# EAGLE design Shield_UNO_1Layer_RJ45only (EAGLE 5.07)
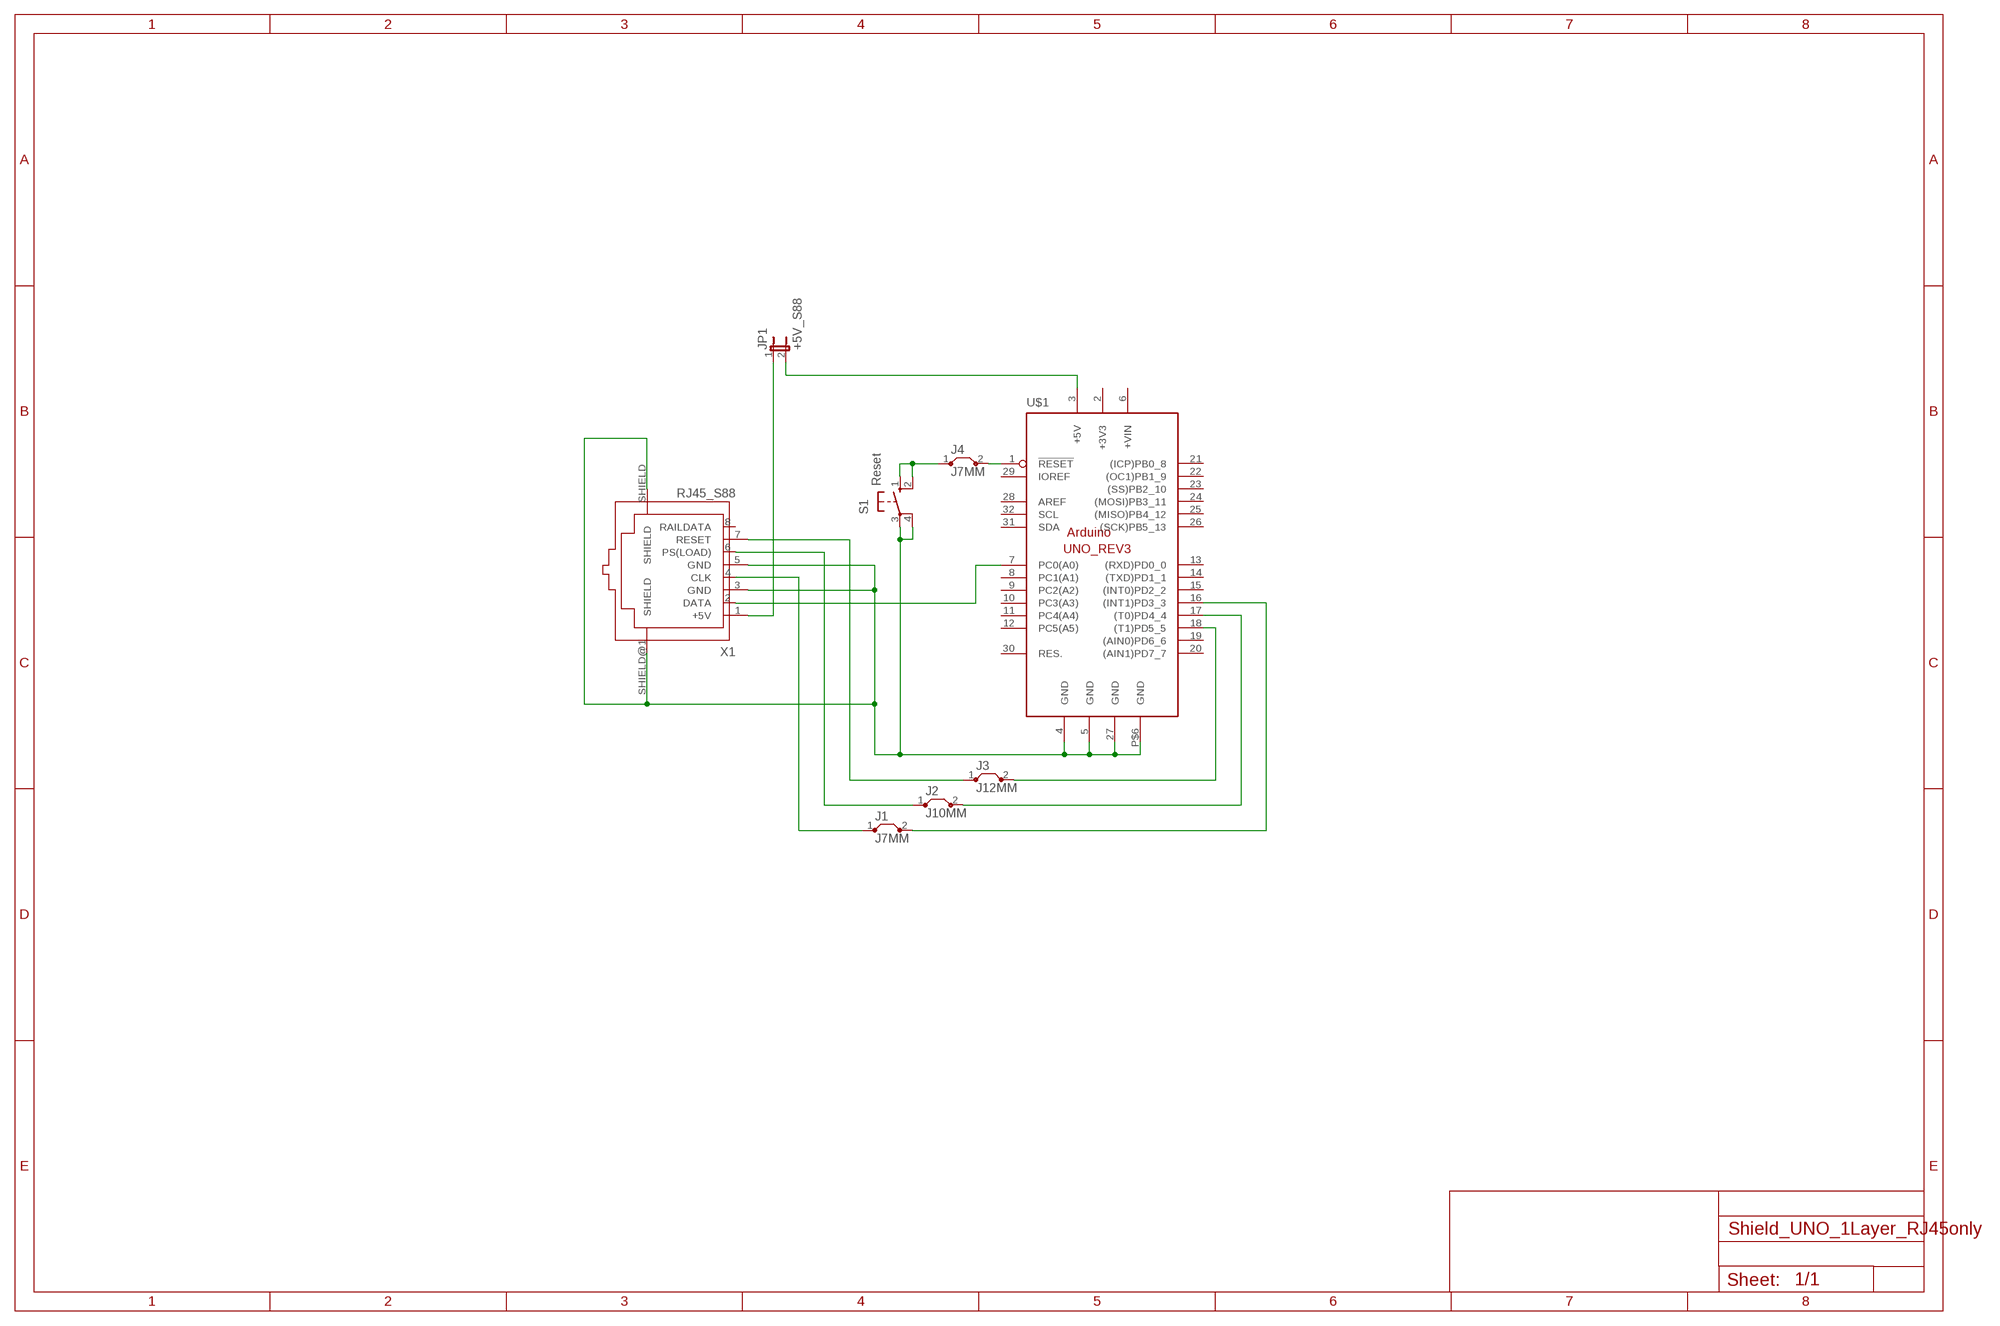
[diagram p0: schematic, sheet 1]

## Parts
J1  J7MM  [07]
J2  J10MM  [10]
J3  J12MM  [12]
J4  J7MM  [07]
JP1  +5V_S88  JP1E  [JP1]
S1  Reset  10-XX  [B3F-10XX]
U$1  ARDUINO_UNO_REV3  [ARDUINO_UNO_REV3_SHORT]
X1  RJ45_S88  RJ45-S88-N  [RJ45-SHIELDED]

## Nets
GND: S1.3(P) S1.4(P1) U$1.4(GND) U$1.5(GND) U$1.27(GND) U$1.P$6(GND) X1.3(GND) X1.5(GND) X1.SHIELD X1.SHIELD@1(SHIELD)
N$1: J4.1 S1.1(S) S1.2(S1)
N$2: J1.2 U$1.16((INT1)PD3_3)
N$3: JP1.2 U$1.3(+5V)
N$4: U$1.7(PC0(A0)) X1.2(DATA)
N$5: J2.2 U$1.17((T0)PD4_4)
N$6: J4.2 U$1.1(!RESET)
N$7: J3.2 U$1.18((T1)PD5_5)
N$8: J3.1 X1.7(RESET)
N$9: J2.1 X1.6(PS(LOAD))
N$10: J1.1 X1.4(CLK)
N$11: JP1.1 X1.1(+5V)
Unconnected: U$1.6(+VIN) U$1.8(PC1(A1)) U$1.9(PC2(A2)) U$1.10(PC3(A3)) U$1.11(PC4(A4)) U$1.12(PC5(A5)) U$1.13((RXD)PD0_0) U$1.14((TXD)PD1_1) U$1.15((INT0)PD2_2) U$1.19((AIN0)PD6_6) U$1.20((AIN1)PD7_7) U$1.21((ICP)PB0_8) U$1.22((OC1)PB1_9) U$1.23((SS)PB2_10) U$1.24((MOSI)PB3_11) U$1.25((MISO)PB4_12) U$1.26((SCK)PB5_13) U$1.28(AREF) U$1.29(IOREF) U$1.30(RES.) U$1.31(SDA) U$1.32(SCL) X1.8(RAILDATA)

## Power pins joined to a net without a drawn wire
+3V3: U$1.2(+3V3)

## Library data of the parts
J1-J4 = jumper:J: Bridge
JP1 = jumper:JP1E: JUMPER
S1 = switch-omron:10-XX: OMRON SWITCH
U$1 = arduino:ARDUINO_UNO_REV3
X1 = con-amphenol-rj45_S88-N:RJ45-S88-N: RJ45 socket Naming: BEL FUSESS-7188S-A-NF TMESS-7188S-A-NF Datasheet: https://www.belfuse.com/resources/drawings/stewartconnector/dr-stw-ss-7188s-a-nf-ss-7188s-a-nf-50.pdf

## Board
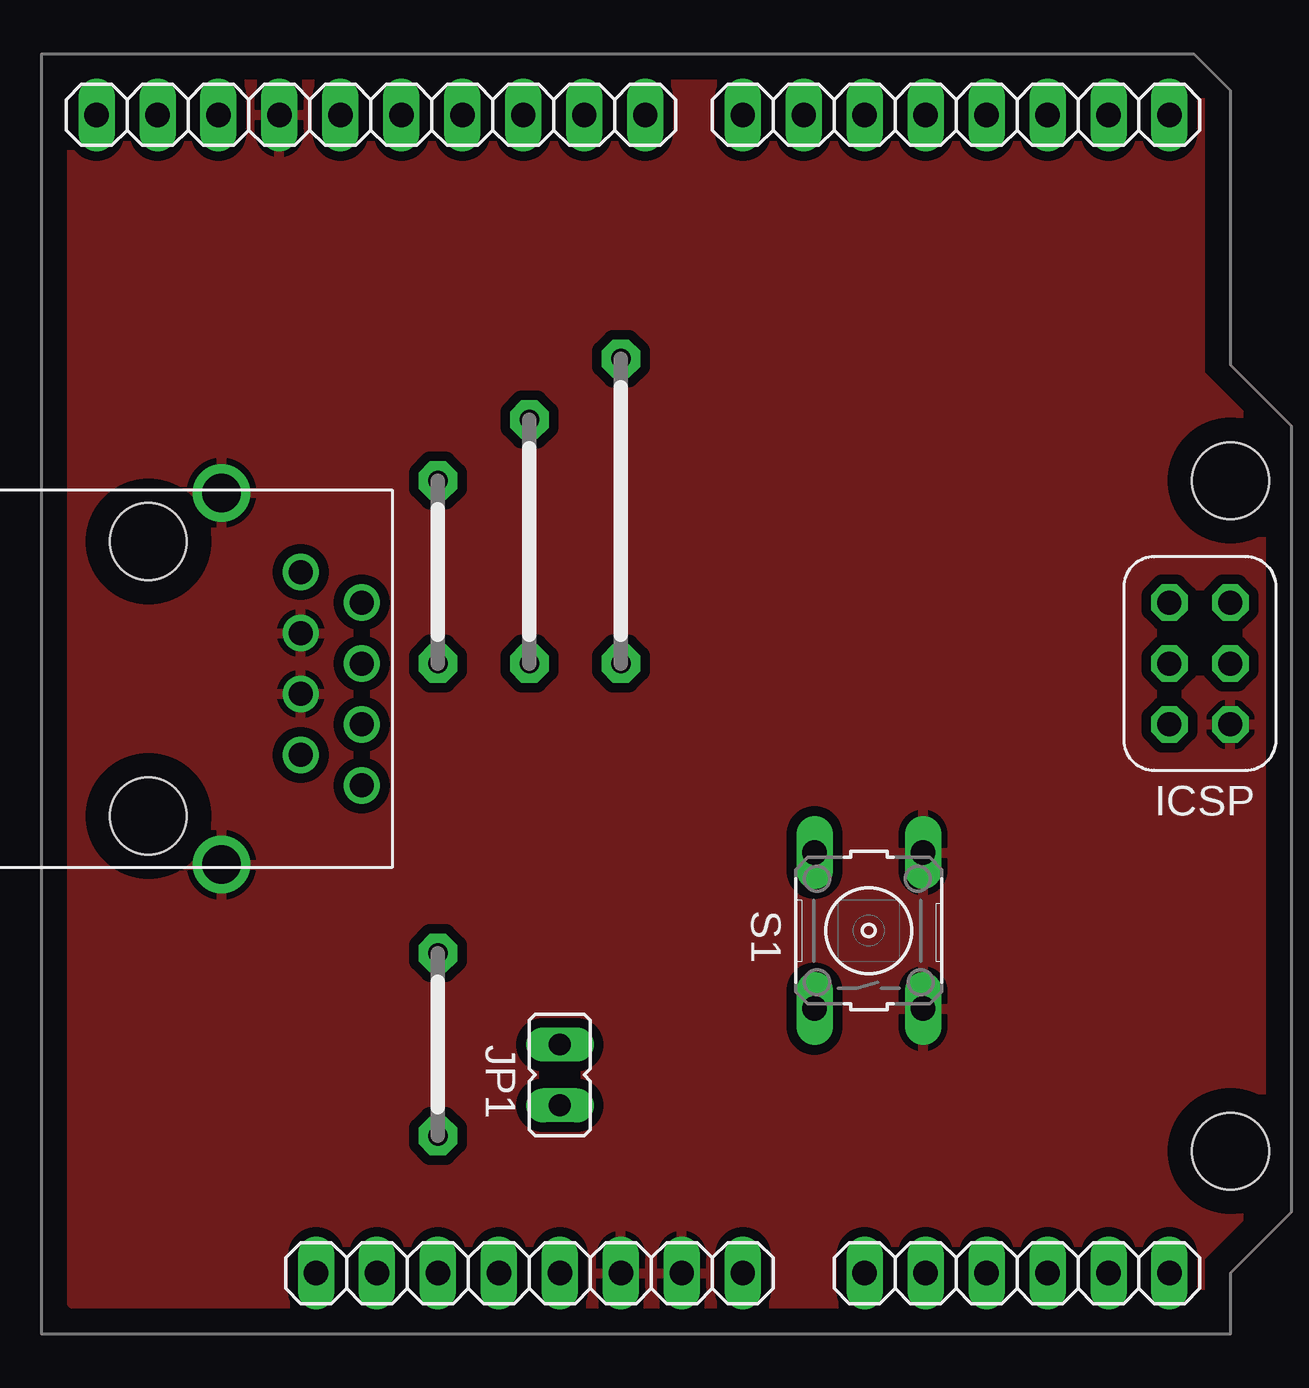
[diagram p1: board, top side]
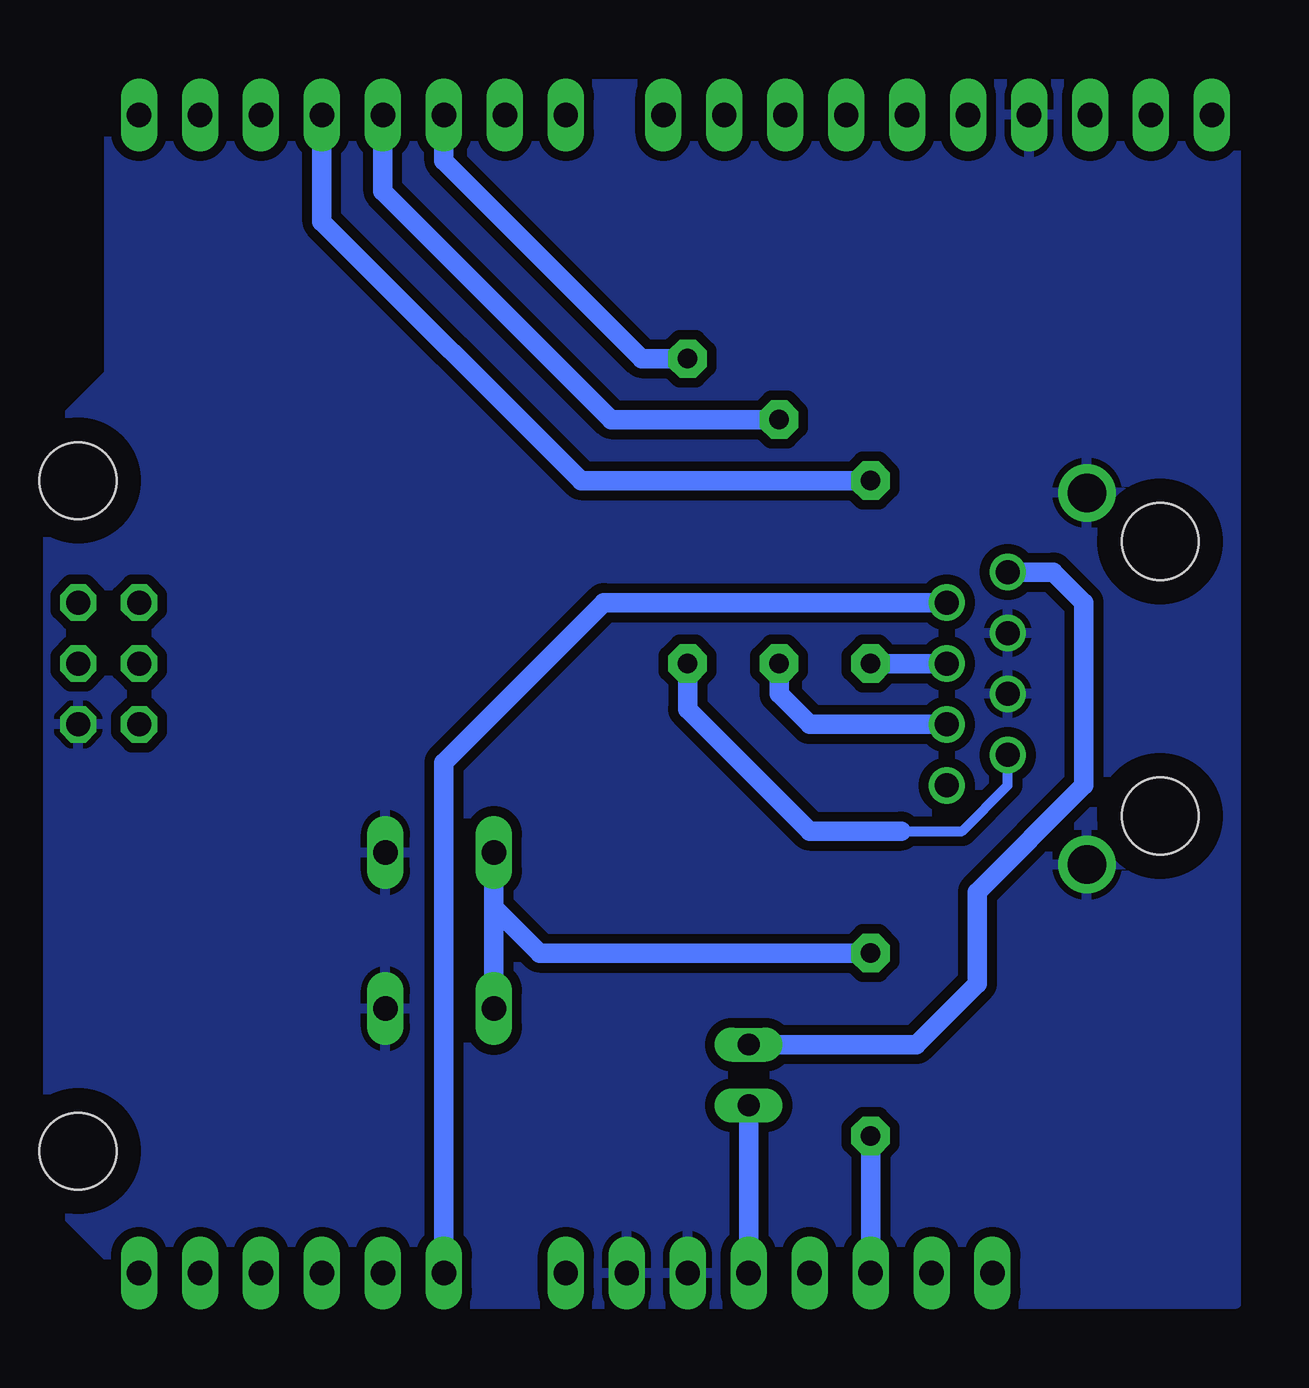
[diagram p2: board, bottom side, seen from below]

No outline drawn. Coordinates in mm, seen from the top.
Copper layers (1*16): Top 0.035mm / dielectric 1.5mm / Bottom 0.035mm
Design rules "default *": minimum track width 16mil, minimum drill 24mil, track to track 16mil, track to pad 16mil, pad to pad 16mil, via to via 16mil, smd to smd 10mil, copper to edge 40mil, drill to drill 20mil, minimum pad ring 10mil, minimum via ring 8mil, stop-mask expansion 4mil, vias tented up to drill 0mil, thermal gap 10mil

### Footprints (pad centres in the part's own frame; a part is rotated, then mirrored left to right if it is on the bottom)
07 = drill 0.813 pad 1.6 octagon: 1 -3.81,0; 2 3.81,0
10 = drill 0.813 pad 1.6 octagon: 1 -5.08,0; 2 5.08,0
12 = drill 0.813 pad 1.6 octagon: 1 -6.35,0; 2 6.35,0
JP1 = drill 0.914 long: 1 0,-1.27; 2 0,1.27
B3F-10XX = drill 1.016 long: 1 -3.251,2.261; 2 3.251,2.261; 3 -3.251,-2.261; 4 3.251,-2.261
ARDUINO_UNO_REV3_SHORT = drill 1.016 long: 1 33.02,2.54; 2 35.56,2.54; 3 38.1,2.54; 4 40.64,2.54; 5 43.18,2.54; 6 45.72,2.54; 7 50.8,2.54; 8 53.34,2.54; 9 55.88,2.54; 10 58.42,2.54; 11 60.96,2.54; 12 63.5,2.54; 13 63.5,50.8; 14 60.96,50.8; 15 58.42,50.8; 16 55.88,50.8; 17 53.34,50.8; 18 50.8,50.8; 19 48.26,50.8; 20 45.72,50.8; 21 41.656,50.8; 22 39.116,50.8; 23 36.576,50.8; 24 34.036,50.8; 25 31.496,50.8; 26 28.956,50.8; 27 26.416,50.8; 28 23.876,50.8; 29 30.48,2.54; 30 27.94,2.54; 31 21.336,50.8; 32 18.796,50.8 | drill 1 octagon: P$1 63.5,30.48; P$2 66.04,30.48; P$3 66.04,27.94; P$4 63.5,27.94; P$5 63.5,25.4; P$6 66.04,25.4 | hole 3.2: 66.04,35.56; 66.04,7.62
RJ45-SHIELDED = drill 1 round: 1 -5.08,7.62; 2 -3.81,10.16; 3 -2.54,7.62; 4 -1.27,10.16; 5 0,7.62; 6 1.27,10.16; 7 2.54,7.62; 8 3.81,10.16 | drill 1.6 round: SHIELD -8.382,4.318; SHIELD@1 7.112,4.318 | hole 3.2: -6.35,1.27; 5.08,1.27

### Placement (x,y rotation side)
J1  21.59,-41.91 90 top
J2  25.4,-40.64 90 top
J3  29.21,-39.37 90 top
J4  21.59,-61.59 270 top
JP1  26.67,-62.87 180 top
S1  39.54,-56.85 90 top
U$1  -11.43,-73.66 0 top
X1  8.26,-46.99 270 top

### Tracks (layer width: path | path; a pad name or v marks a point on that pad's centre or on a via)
GND
  pour Bottom: 6.35,-21.59 52.7,-21.59 53.34,-22.23 53.34,-33.66 55.88,-36.2 55.88,-67.94 53.34,-70.48 53.34,-71.75 52.7,-72.39 6.35,-72.39
  pour Top: 6.35,-21.59 52.7,-21.59 53.34,-22.23 53.34,-33.66 55.88,-36.2 55.88,-67.94 53.34,-70.48 53.34,-71.75 52.7,-72.39 6.35,-72.39
N$1
  Bottom 0.813: S1.2 37.28,-55.88 | 37.28,-55.88 S1.1 | J4.1 35.38,-57.78 37.28,-55.88
N$2
  Bottom 0.813: U$1.16 44.45,-27.3 33.66,-38.1 J1.2
N$3
  Bottom 0.813: JP1.2 U$1.3
N$4
  Bottom 0.813: X1.2 32.7,-43.18 39.37,-49.85 U$1.7
N$5
  Bottom 0.813: U$1.17 41.91,-26.04 32.38,-35.56 J2.2
N$6
  Bottom 0.813: J4.2 U$1.1
N$7
  Bottom 0.813: U$1.18 39.37,-24.77 31.11,-33.02 J3.2
N$8
  Bottom 0.406: X1.7 15.88,-50.8 17.78,-52.7 20.32,-52.7
  Bottom 0.813: 20.32,-52.7 24.13,-52.7 29.21,-47.62 J3.1
N$9
  Bottom 0.813: X1.6 24.13,-48.26 25.4,-46.99 J2.1
N$10
  Bottom 0.813: J1.1 X1.4
N$11
  Bottom 0.813: X1.1 13.97,-41.91 12.7,-43.18 12.7,-50.8 17.14,-55.24 17.14,-59.05 19.68,-61.59 JP1.1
